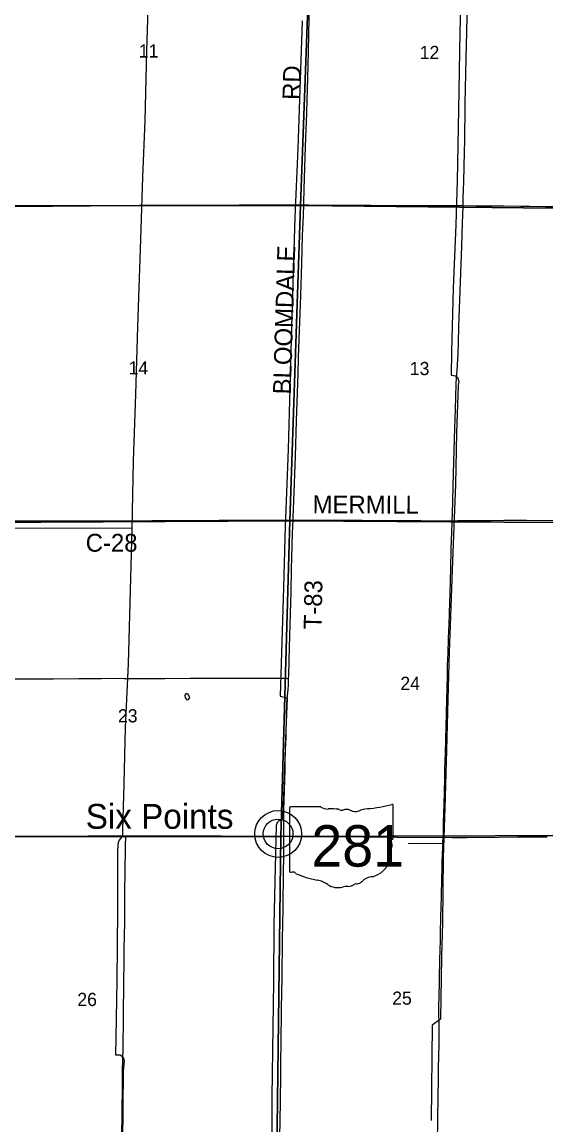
# Model space of a CAD drawing. Extents: x 1443599 to 1910620, y 1028088 to 1361369.
# Drawn here: x 1674173 to 1682963, y 1192606 to 1211112 of the extents above; entities that cross this region are included whole.
import ezdxf

# ---------------------------------------------------------------- set-up
doc = ezdxf.new("R2010")
doc.units = 0
for name, color, linetype in [('GM_X_County_Road', 7, 'Continuous'), ('GM_X_County_Road_Text', 7, 'Continuous'), ('GM_X_Minor_Lake', 7, 'Continuous'), ('GM_X_Minor_River', 7, 'Continuous'), ('GM_X_Section', 7, 'Continuous'), ('GM_X_Section_Text', 7, 'Continuous'), ('GM_X_State_Location', 7, 'Continuous'), ('GM_X_State_Route', 7, 'Continuous'), ('GM_X_State_Shield', 7, 'Continuous'), ('GM_X_Township_Road', 7, 'Continuous'), ('GM_X_Township_Road_Text', 7, 'Continuous'), ('GM_X_Unincorporated', 7, 'Continuous'), ('GM_X_Unincorporated_Location', 7, 'Continuous'), ('GM_X_Unincorporated_Text', 7, 'Continuous')]:
    doc.layers.add(name, color=color, linetype=linetype)

msp = doc.modelspace()

# ---------------------------------------------------------------- linework, layer by layer
at = {"layer": 'GM_X_County_Road'}
for points in [[(1673447, 1202740), (1673756, 1202741), (1674167, 1202742), (1674528, 1202743), (1674791, 1202744), (1675135, 1202745), (1675447, 1202745), (1676136, 1202744), (1676350, 1202746), (1676580, 1202748), (1676957, 1202749), (1677187, 1202750), (1677482, 1202751), (1677827, 1202751), (1678155, 1202753), (1678549, 1202753), (1678721, 1202753)], [(1678721, 1202753), (1678763, 1202753), (1679074, 1202756), (1679879, 1202752), (1680223, 1202748), (1680568, 1202748), (1680864, 1202746), (1681274, 1202744), (1681391, 1202745)], [(1681391, 1202745), (1681487, 1202746), (1681816, 1202750), (1682045, 1202749), (1682259, 1202751), (1682636, 1202754), (1683145, 1202750), (1683309, 1202748), (1683834, 1202739), (1684015, 1202734), (1684092, 1202730)]]:
    msp.add_lwpolyline(points, dxfattribs=at)
at = {"layer": 'GM_X_Minor_Lake'}
msp.add_line((1676907, 1199789), (1676907, 1199775), dxfattribs=at)
msp.add_lwpolyline([(1676907, 1199775), (1676938, 1199738), (1676965, 1199746), (1676989, 1199771), (1676960, 1199832), (1676924, 1199843), (1676900, 1199811), (1676907, 1199789)], dxfattribs=at)
at = {"layer": 'GM_X_Minor_River'}
for points in [[(1681556, 1212411), (1681516, 1210936), (1681496, 1209643), (1681472, 1208448), (1681453, 1207709), (1681407, 1206645), (1681376, 1205585), (1681371, 1205188), (1681413, 1205183), (1681445, 1205174), (1681477, 1205152), (1681499, 1205079), (1681490, 1205015), (1681462, 1204221), (1681448, 1203353), (1681417, 1202650), (1681388, 1201914), (1681355, 1200994), (1681341, 1200537), (1681317, 1199744), (1681293, 1198894), (1681264, 1197925), (1681241, 1197087), (1681227, 1196004), (1681213, 1195429), (1681192, 1194380), (1681054, 1194281), (1681037, 1192682)], [(1676291, 1211514), (1676263, 1210628), (1676232, 1209459), (1676194, 1208511), (1676161, 1207471), (1676109, 1205998), (1676078, 1204868), (1676038, 1203743), (1676013, 1202619), (1675979, 1201364), (1675954, 1200341), (1675905, 1199275), (1675880, 1198331), (1675860, 1197555), (1675856, 1197487), (1675850, 1197453), (1675835, 1197427), (1675805, 1197392), (1675784, 1197348), (1675779, 1197298), (1675777, 1197196), (1675775, 1196209), (1675762, 1195032), (1675749, 1194075), (1675738, 1193783), (1675818, 1193781), (1675871, 1193744), (1675886, 1193688), (1675867, 1193502), (1675854, 1191699)], [(1678875, 1211133), (1678800, 1208992), (1678748, 1207838), (1678695, 1205998), (1678640, 1203939), (1678590, 1202649), (1678562, 1201626), (1678501, 1199800), (1678622, 1199774), (1678588, 1198950), (1678567, 1198273), (1678551, 1197804), (1678550, 1197772), (1678531, 1197728), (1678507, 1197720), (1678475, 1197701), (1678452, 1197681), (1678446, 1197661), (1678435, 1197629), (1678412, 1196687), (1678399, 1195963), (1678392, 1195008), (1678380, 1194242), (1678365, 1193075), (1678362, 1192032)], [(1673349, 1202623), (1676013, 1202619)], [(1681247, 1197328), (1680653, 1197321)]]:
    msp.add_lwpolyline(points, dxfattribs=at)
at = {"layer": 'GM_X_Section'}
for points in [[(1679041, 1213332), (1678843, 1208036), (1673597, 1208030), (1673741, 1213362)], [(1679041, 1213332), (1684284, 1213369), (1684296, 1213220), (1684193, 1207979), (1678843, 1208036)], [(1673597, 1208030), (1678843, 1208036), (1678667, 1202740), (1673439, 1202717)], [(1684193, 1207979), (1684193, 1207809), (1684061, 1202709), (1678667, 1202740), (1678843, 1208036)], [(1678667, 1202740), (1678517, 1197443), (1673255, 1197445), (1673439, 1202717)], [(1678667, 1202740), (1684061, 1202709), (1683913, 1197462), (1678517, 1197443)], [(1673255, 1197445), (1678517, 1197443), (1678448, 1192134), (1673160, 1192114)], [(1678517, 1197443), (1683913, 1197462), (1683747, 1192150), (1678448, 1192134)]]:
    msp.add_lwpolyline(points, close=True, dxfattribs=at)
at = {"layer": 'GM_X_State_Route'}
msp.add_lwpolyline([(1674070, 1197450), (1674398, 1197452), (1674808, 1197455), (1675022, 1197454), (1675284, 1197455), (1675793, 1197458), (1675913, 1197459), (1676220, 1197459), (1677024, 1197456), (1677516, 1197455), (1677943, 1197453), (1678304, 1197452), (1678501, 1197450), (1678564, 1197449), (1678698, 1197447), (1678977, 1197444), (1679896, 1197439), (1680454, 1197435), (1681176, 1197430), (1681240, 1197432), (1681390, 1197431), (1681636, 1197431), (1682161, 1197436), (1682489, 1197439), (1682982, 1197441)], dxfattribs=at)
at = {"layer": 'GM_X_State_Shield'}
for p, q in [((1678659, 1197923), (1678659, 1196866)), ((1679186, 1197941), (1678676, 1197941)), ((1680399, 1197414), (1680399, 1197967)), ((1680399, 1197414), (1680399, 1197414))]:
    msp.add_line(p, q, dxfattribs=at)
for centre, major_axis, start_param, end_param in [((1678679, 1197925), (20.2, 0), 1.712693, 3.28349), ((1679307, 1198063), (196, 0), 4.042523, 4.731795), ((1679372, 1197348), (702, 0), 1.404758, 1.657858), ((1679614, 1197808), (117, 0), 0.950623, 2.079405), ((1680015, 1197618), (371, 0), 1.699011, 2.107814), ((1679780, 1199381), (1845, 0), 4.814394, 5.042369), ((1680380, 1197969), (19.4, 0), 6.141152, 7.989035), ((1679532, 1197930), (56.4, 0), 3.836095, 5.185415), ((1679766, 1197976), (141, 0), 4.081561, 5.145723), ((1680395, 1197374), (30, 0), 1.883978, 3.671073), ((1680204, 1197304), (180, 0), 5.934695, 6.695948), ((1680379, 1197412), (20.7, 0), 5.05454, 6.418171), ((1679883, 1197113), (462, 0), 5.101752, 6.440018), ((1680469, 1197183), (131, 0), 2.387724, 3.262537), ((1678679, 1196864), (20.3, 0), 3.00124, 4.508301), ((1678682, 1196972), (155, 0), 4.665946, 4.897461), ((1678714, 1196805), (56, 0), 0.519207, 1.627899), ((1679421, 1197754), (1333, 0), 4.195997, 4.488961), ((1679023, 1196391), (417, 0), 0.823519, 1.323587), ((1679474, 1196800), (265, 0), 4.026481, 4.996735), ((1679627, 1196434), (217, 0), 1.495662, 1.94098), ((1679647, 1196721), (141, 0), 4.691044, 5.507374), ((1679774, 1196618), (39.7, 0), 1.147584, 2.315152), ((1679757, 1196764), (149, 0), 4.937069, 5.64225), ((1680078, 1196569), (253, 0), 1.647645, 2.488434)]:
    msp.add_ellipse(centre, major_axis=major_axis, ratio=0.8, start_param=start_param, end_param=end_param, dxfattribs=at)
at = {"layer": 'GM_X_Township_Road'}
for points in [[(1678900, 1208043), (1678901, 1208079), (1678907, 1208309), (1678925, 1208851), (1678935, 1209179), (1678944, 1209425), (1678951, 1209605), (1678962, 1209983), (1678974, 1210377), (1678985, 1210886), (1678991, 1211198), (1678994, 1211378), (1679006, 1211821), (1679039, 1212789), (1679045, 1212986), (1679047, 1213085), (1679056, 1213348)], [(1681605, 1209399), (1681606, 1209431), (1681609, 1209743), (1681615, 1209989), (1681624, 1210514), (1681635, 1210941), (1681648, 1211499)], [(1681573, 1208031), (1681577, 1208167), (1681585, 1208430), (1681591, 1208692), (1681597, 1208922), (1681601, 1209135), (1681605, 1209399)], [(1673616, 1208022), (1673730, 1208021), (1673944, 1208022), (1674288, 1208022), (1674682, 1208024), (1675322, 1208029), (1675536, 1208032), (1675913, 1208035), (1676143, 1208039), (1676291, 1208038), (1676553, 1208038), (1676865, 1208039), (1677259, 1208040), (1677571, 1208042), (1677817, 1208043), (1678047, 1208044), (1678277, 1208043), (1678523, 1208043), (1678802, 1208044), (1678900, 1208043)], [(1678721, 1202753), (1678722, 1202797), (1678738, 1203223), (1678759, 1203830), (1678780, 1204421), (1678805, 1205208), (1678813, 1205487), (1678849, 1206521), (1678867, 1207062), (1678880, 1207522), (1678893, 1207866), (1678900, 1208043)], [(1678900, 1208043), (1678982, 1208043), (1679409, 1208040), (1679639, 1208040), (1679868, 1208038), (1680032, 1208039), (1680476, 1208036), (1680722, 1208036), (1681001, 1208035), (1681329, 1208031), (1681573, 1208031)], [(1681391, 1202745), (1681395, 1202853), (1681414, 1203542), (1681436, 1204296), (1681445, 1204608), (1681459, 1205035), (1681465, 1205149), (1681475, 1205264), (1681482, 1205362), (1681489, 1205543), (1681495, 1205723), (1681504, 1206002), (1681540, 1207052), (1681551, 1207347), (1681562, 1207741), (1681572, 1208003), (1681573, 1208031)], [(1681573, 1208031), (1681575, 1208031), (1681789, 1208030), (1682265, 1208026), (1682544, 1208023), (1682691, 1208022), (1682954, 1208019), (1683381, 1208015), (1684021, 1208011), (1684168, 1208012), (1684221, 1208013)], [(1678645, 1200097), (1678647, 1200155), (1678660, 1200615), (1678678, 1201189), (1678687, 1201550), (1678696, 1201927), (1678713, 1202534), (1678721, 1202753)], [(1681316, 1200406), (1681316, 1200410), (1681321, 1200528), (1681330, 1200757), (1681333, 1200902), (1681337, 1201000), (1681343, 1201196), (1681348, 1201360), (1681354, 1201524), (1681365, 1201950), (1681375, 1202262), (1681385, 1202557), (1681390, 1202705), (1681391, 1202745)], [(1681240, 1197432), (1681242, 1197466), (1681247, 1197711), (1681249, 1197792), (1681250, 1197825), (1681255, 1197988), (1681259, 1198201), (1681265, 1198414), (1681269, 1198578), (1681276, 1198841), (1681282, 1199087), (1681288, 1199283), (1681294, 1199512), (1681300, 1199758), (1681305, 1199922), (1681310, 1200152), (1681312, 1200262), (1681314, 1200339), (1681316, 1200406)], [(1673349, 1200091), (1673469, 1200089), (1673650, 1200090), (1673863, 1200092), (1674043, 1200092), (1674257, 1200093), (1674486, 1200092), (1674601, 1200092), (1674699, 1200093), (1675126, 1200096), (1675503, 1200098), (1675683, 1200100), (1675880, 1200099), (1676176, 1200098), (1676389, 1200099), (1676569, 1200099), (1676996, 1200100), (1677258, 1200101), (1677980, 1200103), (1678423, 1200103), (1678570, 1200101), (1678614, 1200099), (1678645, 1200097)], [(1678564, 1197449), (1678564, 1197477), (1678563, 1197777), (1678565, 1197892), (1678574, 1198220), (1678580, 1198397), (1678586, 1198565), (1678589, 1198680), (1678595, 1198893), (1678602, 1199123), (1678611, 1199484), (1678615, 1199664), (1678620, 1199763), (1678625, 1199812), (1678636, 1199910), (1678642, 1199991), (1678645, 1200097)], [(1675841, 1192160), (1675846, 1192438), (1675851, 1192782), (1675857, 1193291), (1675860, 1193521), (1675862, 1193685), (1675867, 1193915), (1675872, 1194046), (1675875, 1194260), (1675877, 1194572), (1675883, 1194867), (1675883, 1195048), (1675884, 1195294), (1675887, 1195557), (1675896, 1196000), (1675896, 1196181), (1675896, 1196460), (1675902, 1196920), (1675906, 1197199), (1675908, 1197314), (1675912, 1197429), (1675913, 1197459)], [(1678492, 1192150), (1678494, 1192165), (1678498, 1192231), (1678500, 1192395), (1678507, 1192985), (1678513, 1193461), (1678515, 1193691), (1678520, 1193954), (1678521, 1194052), (1678523, 1194200), (1678525, 1194315), (1678528, 1194544), (1678533, 1194840), (1678536, 1195070), (1678539, 1195283), (1678542, 1195529), (1678545, 1195775), (1678548, 1195923), (1678552, 1196284), (1678560, 1196842), (1678563, 1197104), (1678564, 1197219), (1678564, 1197350), (1678564, 1197449)], [(1681142, 1192393), (1681147, 1192606), (1681150, 1192737), (1681161, 1193393), (1681162, 1193557), (1681170, 1193967), (1681171, 1194032), (1681173, 1194180), (1681174, 1194327), (1681168, 1194475), (1681168, 1194622), (1681171, 1194737), (1681177, 1195032), (1681178, 1195113), (1681183, 1195326), (1681183, 1195359), (1681184, 1195408), (1681187, 1195506), (1681189, 1195570), (1681192, 1195670), (1681192, 1195719), (1681194, 1195800), (1681196, 1195850), (1681196, 1195915), (1681200, 1195997), (1681202, 1196046), (1681208, 1196308), (1681209, 1196390), (1681212, 1196505), (1681212, 1196553), (1681215, 1196635), (1681218, 1196733), (1681223, 1196913), (1681224, 1196979), (1681229, 1197175), (1681231, 1197226), (1681233, 1197283), (1681234, 1197331), (1681240, 1197432)]]:
    msp.add_lwpolyline(points, dxfattribs=at)
at = {"layer": 'GM_X_Unincorporated'}
for radius in [393, 249]:
    msp.add_circle((1678470, 1197489), radius, dxfattribs=at)
at = {"layer": 'GM_X_Unincorporated_Location'}
msp.add_line((1678470, 1197489), (1678470, 1197489), dxfattribs=at)

# ---------------------------------------------------------------- texts
at = {"layer": 'GM_X_County_Road_Text'}
for s, rotation, p in [('MERMILL', 359.8508, (1679047, 1202868)), ('C-28', 0, (1675241, 1202224))]:
    msp.add_text(s, height=300, rotation=rotation, dxfattribs=at).set_placement(p)
at = {"layer": 'GM_X_Section_Text'}
for s, p in [('11', (1676132, 1210516)), ('12', (1680846, 1210491)), ('14', (1675960, 1205198)), ('13', (1680679, 1205188)), ('24', (1680521, 1199905)), ('23', (1675782, 1199360)), ('26', (1675100, 1194601)), ('25', (1680384, 1194623))]:
    msp.add_text(s, height=221, rotation=0, dxfattribs=at).set_placement(p)
at = {"layer": 'GM_X_State_Location'}
msp.add_text('281', height=1, rotation=0, dxfattribs=at).set_placement((1679157, 1197251))
for s in ['s', 'r']:
    msp.add_text(s, height=1, dxfattribs=at).set_placement((1679510, 1197324))
at = {"layer": 'GM_X_State_Shield'}
msp.add_text('281', height=696.1, dxfattribs=at).set_placement((1679028, 1196940))
at = {"layer": 'GM_X_Township_Road_Text'}
for s, rotation, p in [('RD', 88.5194, (1678841, 1209802)), ('BLOOMDALE', 88.2511, (1678682, 1204861)), ('T-83', 88.957, (1679198, 1200920))]:
    msp.add_text(s, height=300, rotation=rotation, dxfattribs=at).set_placement(p)
at = {"layer": 'GM_X_Unincorporated_Text'}
msp.add_text('Six Points', height=417, rotation=0, dxfattribs=at).set_placement((1675241, 1197575))

doc.saveas('drawing.dxf')
